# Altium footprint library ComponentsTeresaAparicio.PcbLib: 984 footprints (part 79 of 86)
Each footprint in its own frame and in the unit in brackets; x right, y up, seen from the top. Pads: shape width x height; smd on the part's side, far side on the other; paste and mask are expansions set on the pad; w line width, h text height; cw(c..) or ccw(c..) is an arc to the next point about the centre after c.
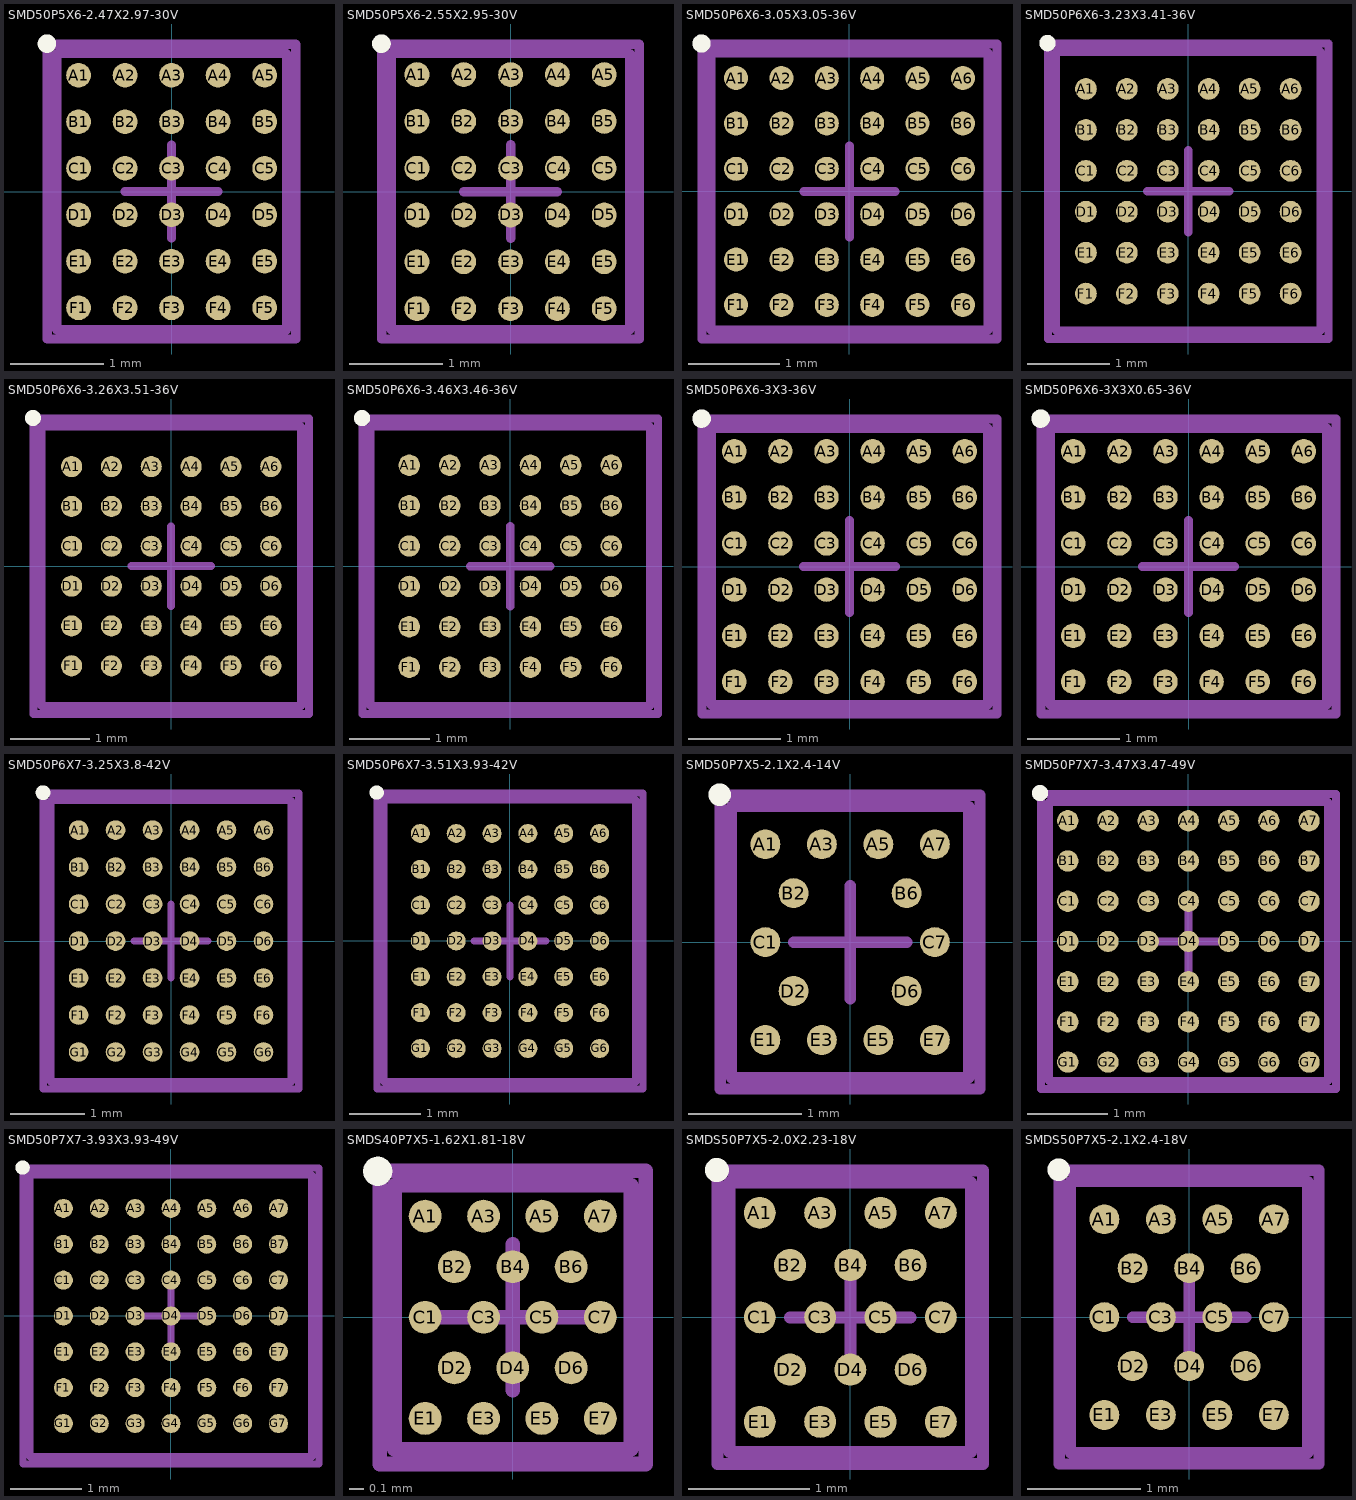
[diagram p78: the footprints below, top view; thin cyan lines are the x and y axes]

## SMD50P5X6-2.47X2.97-30V [mm] "Micro SMD, 30-Leads, Body 2.97x2.47mm, Pitch 0.5mm, NSC Recommended"
height 0.68
pads (30):
  round 0.265 smd paste-0.132 mask+0.05: A1(-1,1.25) A2(-0.5,1.25) A3(0,1.25) A4(0.5,1.25) A5(1,1.25) B1(-1,0.75) B2(-0.5,0.75) B3(0,0.75) B4(0.5,0.75) B5(1,0.75) C1(-1,0.25) C2(-0.5,0.25) C3(0,0.25) C4(0.5,0.25) C5(1,0.25) D1(-1,-0.25) D2(-0.5,-0.25) D3(0,-0.25) D4(0.5,-0.25) D5(1,-0.25) E1(-1,-0.75) E2(-0.5,-0.75) E3(0,-0.75) E4(0.5,-0.75) E5(1,-0.75) F1(-1,-1.25) F2(-0.5,-1.25) F3(0,-1.25) F4(0.5,-1.25) F5(1,-1.25)
Top Overlay:
  circle w0.1: c-1.34,1.59 r0.05
Top Paste:
  drawing of 270 lines, arcs and shapes, not listed
Mechanical 13:
  lines w0.1: -1.235,-1.485 -1.235,1.485 1.235,1.485 1.235,-1.485 -1.235,-1.485
Mechanical 15:
  lines w0.1: -0.5,0 0.5,0 ; 0,-0.5 0,0.5 ; -1.335,-1.585 -1.335,1.585 1.335,1.585 1.335,-1.585 -1.335,-1.585
3D body: height 0.68, standoff 0, extent -1.235,-1.49 1.235,1.49

## SMD50P5X6-2.55X2.95-30V [mm] "Micro SMD, 30-Leads, Body 2.95x2.55mm, Pitch 0.5mm, NSC Recommended"
height 0.68
pads (30):
  round 0.265 smd paste-0.132 mask+0.05: A1(-1,1.25) A2(-0.5,1.25) A3(0,1.25) A4(0.5,1.25) A5(1,1.25) B1(-1,0.75) B2(-0.5,0.75) B3(0,0.75) B4(0.5,0.75) B5(1,0.75) C1(-1,0.25) C2(-0.5,0.25) C3(0,0.25) C4(0.5,0.25) C5(1,0.25) D1(-1,-0.25) D2(-0.5,-0.25) D3(0,-0.25) D4(0.5,-0.25) D5(1,-0.25) E1(-1,-0.75) E2(-0.5,-0.75) E3(0,-0.75) E4(0.5,-0.75) E5(1,-0.75) F1(-1,-1.25) F2(-0.5,-1.25) F3(0,-1.25) F4(0.5,-1.25) F5(1,-1.25)
Top Overlay:
  circle w0.1: c-1.38,1.58 r0.05
Top Paste:
  drawing of 270 lines, arcs and shapes, not listed
Mechanical 13:
  lines w0.1: -1.275,-1.475 -1.275,1.475 1.275,1.475 1.275,-1.475 -1.275,-1.475
Mechanical 15:
  lines w0.1: -0.5,0 0.5,0 ; 0,-0.5 0,0.5 ; -1.375,-1.575 -1.375,1.575 1.375,1.575 1.375,-1.575 -1.375,-1.575
3D body: height 0.68, standoff 0, extent -1.274,-1.474 1.274,1.474

## SMD50P6X6-3.05X3.05-36V [mm] "Micro SMD, 36-Leads, Body 3.05x3.05mm, Pitch 0.5mm, NSC Recommended"
height 0.73
pads (36):
  round 0.265 smd paste-0.132 mask+0.05: A1(-1.25,1.25) A2(-0.75,1.25) A3(-0.25,1.25) A4(0.25,1.25) A5(0.75,1.25) A6(1.25,1.25) B1(-1.25,0.75) B2(-0.75,0.75) B3(-0.25,0.75) B4(0.25,0.75) B5(0.75,0.75) B6(1.25,0.75) C1(-1.25,0.25) C2(-0.75,0.25) C3(-0.25,0.25) C4(0.25,0.25) C5(0.75,0.25) C6(1.25,0.25) D1(-1.25,-0.25) D2(-0.75,-0.25) D3(-0.25,-0.25) D4(0.25,-0.25) D5(0.75,-0.25) D6(1.25,-0.25) E1(-1.25,-0.75) E2(-0.75,-0.75) E3(-0.25,-0.75) E4(0.25,-0.75) E5(0.75,-0.75) E6(1.25,-0.75) F1(-1.25,-1.25) F2(-0.75,-1.25) F3(-0.25,-1.25) F4(0.25,-1.25) F5(0.75,-1.25) F6(1.25,-1.25)
Top Overlay:
  circle w0.1: c-1.63,1.63 r0.05
Top Paste:
  drawing of 324 lines, arcs and shapes, not listed
Mechanical 13:
  lines w0.1: -1.525,-1.525 1.525,-1.525 1.525,1.525 -1.525,1.525 -1.525,-1.525
Mechanical 15:
  lines w0.1: -0.5,0 0.5,0 ; 0,-0.5 0,0.5 ; -1.625,-1.625 1.625,-1.625 1.625,1.625 -1.625,1.625 -1.625,-1.625
3D body: height 0.73, standoff 0, extent -1.524,-1.524 1.524,1.524

## SMD50P6X6-3.23X3.41-36V [mm] "Micro SMD, 36-Leads, Body 3.41x3.23mm, Pitch 0.5mm, NSC Recommended"
height 0.68
pads (36):
  round 0.265 smd paste-0.132 mask+0.05: A1(-1.25,1.25) A2(-0.75,1.25) A3(-0.25,1.25) A4(0.25,1.25) A5(0.75,1.25) A6(1.25,1.25) B1(-1.25,0.75) B2(-0.75,0.75) B3(-0.25,0.75) B4(0.25,0.75) B5(0.75,0.75) B6(1.25,0.75) C1(-1.25,0.25) C2(-0.75,0.25) C3(-0.25,0.25) C4(0.25,0.25) C5(0.75,0.25) C6(1.25,0.25) D1(-1.25,-0.25) D2(-0.75,-0.25) D3(-0.25,-0.25) D4(0.25,-0.25) D5(0.75,-0.25) D6(1.25,-0.25) E1(-1.25,-0.75) E2(-0.75,-0.75) E3(-0.25,-0.75) E4(0.25,-0.75) E5(0.75,-0.75) E6(1.25,-0.75) F1(-1.25,-1.25) F2(-0.75,-1.25) F3(-0.25,-1.25) F4(0.25,-1.25) F5(0.75,-1.25) F6(1.25,-1.25)
Top Overlay:
  circle w0.1: c-1.72,1.81 r0.05
Top Paste:
  drawing of 324 lines, arcs and shapes, not listed
Mechanical 13:
  lines w0.1: -1.615,-1.705 1.615,-1.705 1.615,1.705 -1.615,1.705 -1.615,-1.705
Mechanical 15:
  lines w0.1: -0.5,0 0.5,0 ; 0,-0.5 0,0.5 ; -1.715,-1.805 1.715,-1.805 1.715,1.805 -1.715,1.805 -1.715,-1.805
3D body: height 0.68, standoff 0, extent -1.614,-1.704 1.614,1.704

## SMD50P6X6-3.26X3.51-36V [mm] "Micro SMD, 36-Leads, Body 3.51x3.26mm, Pitch 0.5mm, NSC Recommended"
height 0.68
pads (36):
  round 0.265 smd paste-0.132 mask+0.05: A1(-1.25,1.25) A2(-0.75,1.25) A3(-0.25,1.25) A4(0.25,1.25) A5(0.75,1.25) A6(1.25,1.25) B1(-1.25,0.75) B2(-0.75,0.75) B3(-0.25,0.75) B4(0.25,0.75) B5(0.75,0.75) B6(1.25,0.75) C1(-1.25,0.25) C2(-0.75,0.25) C3(-0.25,0.25) C4(0.25,0.25) C5(0.75,0.25) C6(1.25,0.25) D1(-1.25,-0.25) D2(-0.75,-0.25) D3(-0.25,-0.25) D4(0.25,-0.25) D5(0.75,-0.25) D6(1.25,-0.25) E1(-1.25,-0.75) E2(-0.75,-0.75) E3(-0.25,-0.75) E4(0.25,-0.75) E5(0.75,-0.75) E6(1.25,-0.75) F1(-1.25,-1.25) F2(-0.75,-1.25) F3(-0.25,-1.25) F4(0.25,-1.25) F5(0.75,-1.25) F6(1.25,-1.25)
Top Overlay:
  circle w0.1: c-1.735,1.86 r0.05
Top Paste:
  drawing of 324 lines, arcs and shapes, not listed
Mechanical 13:
  lines w0.1: -1.63,-1.755 1.63,-1.755 1.63,1.755 -1.63,1.755 -1.63,-1.755
Mechanical 15:
  lines w0.1: -0.5,0 0.5,0 ; 0,-0.5 0,0.5 ; -1.73,-1.855 1.73,-1.855 1.73,1.855 -1.73,1.855 -1.73,-1.855
3D body: height 0.68, standoff 0, extent -1.629,-1.754 1.629,1.754

## SMD50P6X6-3.46X3.46-36V [mm] "Micro SMD, 36-Leads, Body 3.46x3.46mm, Pitch 0.5mm, NSC Recommended"
height 0.68
pads (36):
  round 0.265 smd paste-0.132 mask+0.05: A1(-1.25,1.25) A2(-0.75,1.25) A3(-0.25,1.25) A4(0.25,1.25) A5(0.75,1.25) A6(1.25,1.25) B1(-1.25,0.75) B2(-0.75,0.75) B3(-0.25,0.75) B4(0.25,0.75) B5(0.75,0.75) B6(1.25,0.75) C1(-1.25,0.25) C2(-0.75,0.25) C3(-0.25,0.25) C4(0.25,0.25) C5(0.75,0.25) C6(1.25,0.25) D1(-1.25,-0.25) D2(-0.75,-0.25) D3(-0.25,-0.25) D4(0.25,-0.25) D5(0.75,-0.25) D6(1.25,-0.25) E1(-1.25,-0.75) E2(-0.75,-0.75) E3(-0.25,-0.75) E4(0.25,-0.75) E5(0.75,-0.75) E6(1.25,-0.75) F1(-1.25,-1.25) F2(-0.75,-1.25) F3(-0.25,-1.25) F4(0.25,-1.25) F5(0.75,-1.25) F6(1.25,-1.25)
Top Overlay:
  circle w0.1: c-1.835,1.835 r0.05
Top Paste:
  drawing of 324 lines, arcs and shapes, not listed
Mechanical 13:
  lines w0.1: -1.73,-1.73 1.73,-1.73 1.73,1.73 -1.73,1.73 -1.73,-1.73
Mechanical 15:
  lines w0.1: -0.5,0 0.5,0 ; 0,-0.5 0,0.5 ; -1.83,-1.83 1.83,-1.83 1.83,1.83 -1.83,1.83 -1.83,-1.83
3D body: height 0.68, standoff 0, extent -1.73,-1.73 1.73,1.73

## SMD50P6X6-3X3-36V [mm] "Micro SMD, 36-Leads, Body 3x3mm, Pitch 0.5mm, NSC Recommended"
height 0.68
pads (36):
  round 0.265 smd paste-0.132 mask+0.05: A1(-1.25,1.25) A2(-0.75,1.25) A3(-0.25,1.25) A4(0.25,1.25) A5(0.75,1.25) A6(1.25,1.25) B1(-1.25,0.75) B2(-0.75,0.75) B3(-0.25,0.75) B4(0.25,0.75) B5(0.75,0.75) B6(1.25,0.75) C1(-1.25,0.25) C2(-0.75,0.25) C3(-0.25,0.25) C4(0.25,0.25) C5(0.75,0.25) C6(1.25,0.25) D1(-1.25,-0.25) D2(-0.75,-0.25) D3(-0.25,-0.25) D4(0.25,-0.25) D5(0.75,-0.25) D6(1.25,-0.25) E1(-1.25,-0.75) E2(-0.75,-0.75) E3(-0.25,-0.75) E4(0.25,-0.75) E5(0.75,-0.75) E6(1.25,-0.75) F1(-1.25,-1.25) F2(-0.75,-1.25) F3(-0.25,-1.25) F4(0.25,-1.25) F5(0.75,-1.25) F6(1.25,-1.25)
Top Overlay:
  circle w0.1: c-1.605,1.605 r0.05
Top Paste:
  drawing of 324 lines, arcs and shapes, not listed
Mechanical 13:
  lines w0.1: -1.5,-1.5 1.5,-1.5 1.5,1.5 -1.5,1.5 -1.5,-1.5
Mechanical 15:
  lines w0.1: -0.5,0 0.5,0 ; 0,-0.5 0,0.5 ; -1.6,-1.6 1.6,-1.6 1.6,1.6 -1.6,1.6 -1.6,-1.6
3D body: height 0.68, standoff 0, extent -1.499,-1.499 1.499,1.499

## SMD50P6X6-3X3X0.65-36V [mm] "Micro SMD, 36-Leads, Body 3x3mm, Pitch 0.5mm, NSC Recommended"
height 0.73
pads (36):
  round 0.265 smd paste-0.132 mask+0.05: A1(-1.25,1.25) A2(-0.75,1.25) A3(-0.25,1.25) A4(0.25,1.25) A5(0.75,1.25) A6(1.25,1.25) B1(-1.25,0.75) B2(-0.75,0.75) B3(-0.25,0.75) B4(0.25,0.75) B5(0.75,0.75) B6(1.25,0.75) C1(-1.25,0.25) C2(-0.75,0.25) C3(-0.25,0.25) C4(0.25,0.25) C5(0.75,0.25) C6(1.25,0.25) D1(-1.25,-0.25) D2(-0.75,-0.25) D3(-0.25,-0.25) D4(0.25,-0.25) D5(0.75,-0.25) D6(1.25,-0.25) E1(-1.25,-0.75) E2(-0.75,-0.75) E3(-0.25,-0.75) E4(0.25,-0.75) E5(0.75,-0.75) E6(1.25,-0.75) F1(-1.25,-1.25) F2(-0.75,-1.25) F3(-0.25,-1.25) F4(0.25,-1.25) F5(0.75,-1.25) F6(1.25,-1.25)
Top Overlay:
  circle w0.1: c-1.605,1.605 r0.05
Top Paste:
  drawing of 324 lines, arcs and shapes, not listed
Mechanical 13:
  lines w0.1: -1.5,-1.5 1.5,-1.5 1.5,1.5 -1.5,1.5 -1.5,-1.5
Mechanical 15:
  lines w0.1: -0.5,0 0.5,0 ; 0,-0.5 0,0.5 ; -1.6,-1.6 1.6,-1.6 1.6,1.6 -1.6,1.6 -1.6,-1.6
3D body: height 0.73, standoff 0, extent -1.499,-1.499 1.499,1.499

## SMD50P6X7-3.25X3.8-42V [mm] "Micro SMD, 42-Leads, Body 3.8x3.25mm, Pitch 0.5mm, NSC Recommended"
height 0.73
pads (42):
  round 0.265 smd paste-0.132 mask+0.05: A1(-1.25,1.5) A2(-0.75,1.5) A3(-0.25,1.5) A4(0.25,1.5) A5(0.75,1.5) A6(1.25,1.5) B1(-1.25,1) B2(-0.75,1) B3(-0.25,1) B4(0.25,1) B5(0.75,1) B6(1.25,1) C1(-1.25,0.5) C2(-0.75,0.5) C3(-0.25,0.5) C4(0.25,0.5) C5(0.75,0.5) C6(1.25,0.5) D1(-1.25,0) D2(-0.75,0) D3(-0.25,0) D4(0.25,0) D5(0.75,0) D6(1.25,0) E1(-1.25,-0.5) E2(-0.75,-0.5) E3(-0.25,-0.5) E4(0.25,-0.5) E5(0.75,-0.5) E6(1.25,-0.5) F1(-1.25,-1) F2(-0.75,-1) F3(-0.25,-1) F4(0.25,-1) F5(0.75,-1) F6(1.25,-1) G1(-1.25,-1.5) G2(-0.75,-1.5) G3(-0.25,-1.5) G4(0.25,-1.5) G5(0.75,-1.5) G6(1.25,-1.5)
Top Overlay:
  circle w0.1: c-1.73,2.005 r0.05
Top Paste:
  drawing of 378 lines, arcs and shapes, not listed
Mechanical 13:
  lines w0.1: -1.625,-1.9 -1.625,1.9 1.625,1.9 1.625,-1.9 -1.625,-1.9
Mechanical 15:
  lines w0.1: -0.5,0 0.5,0 ; 0,-0.5 0,0.5 ; -1.725,-2 -1.725,2 1.725,2 1.725,-2 -1.725,-2
3D body: height 0.73, standoff 0, extent -1.624,-1.899 1.624,1.899

## SMD50P6X7-3.51X3.93-42V [mm] "Micro SMD, 42-Leads, Body 3.93x3.51mm, Pitch 0.5mm, NSC Recommended"
height 0.68
pads (42):
  round 0.265 smd paste-0.132 mask+0.05: A1(-1.25,1.5) A2(-0.75,1.5) A3(-0.25,1.5) A4(0.25,1.5) A5(0.75,1.5) A6(1.25,1.5) B1(-1.25,1) B2(-0.75,1) B3(-0.25,1) B4(0.25,1) B5(0.75,1) B6(1.25,1) C1(-1.25,0.5) C2(-0.75,0.5) C3(-0.25,0.5) C4(0.25,0.5) C5(0.75,0.5) C6(1.25,0.5) D1(-1.25,0) D2(-0.75,0) D3(-0.25,0) D4(0.25,0) D5(0.75,0) D6(1.25,0) E1(-1.25,-0.5) E2(-0.75,-0.5) E3(-0.25,-0.5) E4(0.25,-0.5) E5(0.75,-0.5) E6(1.25,-0.5) F1(-1.25,-1) F2(-0.75,-1) F3(-0.25,-1) F4(0.25,-1) F5(0.75,-1) F6(1.25,-1) G1(-1.25,-1.5) G2(-0.75,-1.5) G3(-0.25,-1.5) G4(0.25,-1.5) G5(0.75,-1.5) G6(1.25,-1.5)
Top Overlay:
  circle w0.1: c-1.86,2.07 r0.05
Top Paste:
  drawing of 378 lines, arcs and shapes, not listed
Mechanical 13:
  lines w0.1: -1.755,-1.965 1.755,-1.965 1.755,1.965 -1.755,1.965 -1.755,-1.965
Mechanical 15:
  lines w0.1: -0.5,0 0.5,0 ; 0,-0.5 0,0.5 ; -1.855,-2.065 1.855,-2.065 1.855,2.065 -1.855,2.065 -1.855,-2.065
3D body: height 0.68, standoff 0, extent -1.754,-1.964 1.754,1.964

## SMD50P7X5-2.1X2.4-14V [mm] "Micro SMD, 18-Leads, Body 2.41x2.1mm, Pitch 0.5mm, NSC Recommended"
height 0.68
pads (14):
  round 0.265 smd paste-0.132 mask+0.05: A1(-0.75,0.866) A3(-0.25,0.866) A5(0.25,0.866) A7(0.75,0.866) B2(-0.5,0.433) B6(0.5,0.433) C1(-0.75,0) C7(0.75,0) D2(-0.5,-0.433) D6(0.5,-0.433) E1(-0.75,-0.866) E3(-0.25,-0.866) E5(0.25,-0.866) E7(0.75,-0.866)
Top Overlay:
  circle w0.1: c-1.155,1.305 r0.05
Top Paste:
  circle w0.05: c-0.7,0.816 r0.025
  circle w0.05: c-0.85,0.966 r0.025
  circle w0.05: c-0.85,0.816 r0.025
  circle w0.05: c-0.7,0.966 r0.025
  circle w0.05: c0.85,0.816 r0.025
  circle w0.05: c0.7,0.966 r0.025
  circle w0.05: c0.7,0.816 r0.025
  circle w0.05: c0.85,0.966 r0.025
  circle w0.05: c0.85,-0.816 r0.025
  circle w0.05: c0.7,-0.966 r0.025
  circle w0.05: c0.7,-0.816 r0.025
  circle w0.05: c0.85,-0.966 r0.025
  circle w0.05: c-0.7,-0.966 r0.025
  circle w0.05: c-0.85,-0.816 r0.025
  circle w0.05: c-0.85,-0.966 r0.025
  circle w0.05: c-0.7,-0.816 r0.025
  circle w0.05: c0.575,0.508 r0.025
  circle w0.05: c0.425,0.358 r0.025
  circle w0.05: c0.425,0.508 r0.025
  circle w0.05: c0.575,0.358 r0.025
  circle w0.05: c0.325,0.816 r0.025
  circle w0.05: c0.175,0.966 r0.025
  circle w0.05: c0.175,0.816 r0.025
  circle w0.05: c0.325,0.966 r0.025
  circle w0.05: c-0.175,0.816 r0.025
  circle w0.05: c-0.325,0.966 r0.025
  circle w0.05: c-0.325,0.816 r0.025
  circle w0.05: c-0.175,0.966 r0.025
  circle w0.05: c0.575,-0.508 r0.025
  circle w0.05: c0.425,-0.358 r0.025
  circle w0.05: c0.425,-0.508 r0.025
  circle w0.05: c0.575,-0.358 r0.025
  circle w0.05: c-0.425,0.358 r0.025
  circle w0.05: c-0.575,0.508 r0.025
  circle w0.05: c-0.575,0.358 r0.025
  circle w0.05: c-0.425,0.508 r0.025
  circle w0.05: c-0.7,-0.075 r0.025
  circle w0.05: c-0.85,0.075 r0.025
  circle w0.05: c-0.85,-0.075 r0.025
  circle w0.05: c-0.7,0.075 r0.025
  circle w0.05: c-0.425,-0.358 r0.025
  circle w0.05: c-0.575,-0.508 r0.025
  circle w0.05: c-0.575,-0.358 r0.025
  circle w0.05: c-0.425,-0.508 r0.025
  circle w0.05: c0.325,-0.816 r0.025
  circle w0.05: c0.175,-0.966 r0.025
  circle w0.05: c0.175,-0.816 r0.025
  circle w0.05: c0.325,-0.966 r0.025
  circle w0.05: c-0.175,-0.816 r0.025
  circle w0.05: c-0.325,-0.966 r0.025
  circle w0.05: c-0.325,-0.816 r0.025
  circle w0.05: c-0.175,-0.966 r0.025
  circle w0.05: c0.85,0.075 r0.025
  circle w0.05: c0.7,-0.075 r0.025
  circle w0.05: c0.7,0.075 r0.025
  circle w0.05: c0.85,-0.075 r0.025
  region: -0.85,0.966 -0.85,0.816 -0.7,0.816 -0.7,0.966
  region: -0.65,0.816 -0.65,0.966 -0.7,0.966 -0.7,0.816
  region: -0.7,1.016 -0.85,1.016 -0.85,0.966 -0.7,0.966
  region: -0.9,0.966 -0.9,0.816 -0.85,0.816 -0.85,0.966
  rectangle: -0.85,0.766 -0.7,0.816
  region: 0.7,0.966 0.7,0.816 0.85,0.816 0.85,0.966
  region: 0.9,0.816 0.9,0.966 0.85,0.966 0.85,0.816
  region: 0.85,1.016 0.7,1.016 0.7,0.966 0.85,0.966
  region: 0.65,0.966 0.65,0.816 0.7,0.816 0.7,0.966
  rectangle: 0.7,0.766 0.85,0.816
  rectangle: 0.7,-1.016 0.85,-0.966
  region: 0.65,-0.816 0.65,-0.966 0.7,-0.966 0.7,-0.816
  region: 0.85,-0.766 0.7,-0.766 0.7,-0.816 0.85,-0.816
  region: 0.9,-0.966 0.9,-0.816 0.85,-0.816 0.85,-0.966
  region: 0.7,-0.816 0.7,-0.966 0.85,-0.966 0.85,-0.816
  region: -0.85,-0.816 -0.85,-0.966 -0.7,-0.966 -0.7,-0.816
  region: -0.65,-0.966 -0.65,-0.816 -0.7,-0.816 -0.7,-0.966
  region: -0.7,-0.766 -0.85,-0.766 -0.85,-0.816 -0.7,-0.816
  region: -0.9,-0.816 -0.9,-0.966 -0.85,-0.966 -0.85,-0.816
  rectangle: -0.85,-1.016 -0.7,-0.966
  rectangle: 0.425,0.308 0.575,0.358
  region: 0.375,0.508 0.375,0.358 0.425,0.358 0.425,0.508
  region: 0.575,0.558 0.425,0.558 0.425,0.508 0.575,0.508
  region: 0.625,0.358 0.625,0.508 0.575,0.508 0.575,0.358
  region: 0.425,0.508 0.425,0.358 0.575,0.358 0.575,0.508
  region: 0.175,0.966 0.175,0.816 0.325,0.816 0.325,0.966
  region: 0.375,0.816 0.375,0.966 0.325,0.966 0.325,0.816
  region: 0.325,1.016 0.175,1.016 0.175,0.966 0.325,0.966
  region: 0.125,0.966 0.125,0.816 0.175,0.816 0.175,0.966
  rectangle: 0.175,0.766 0.325,0.816
  region: -0.325,0.966 -0.325,0.816 -0.175,0.816 -0.175,0.966
  region: -0.125,0.816 -0.125,0.966 -0.175,0.966 -0.175,0.816
  region: -0.175,1.016 -0.325,1.016 -0.325,0.966 -0.175,0.966
  region: -0.375,0.966 -0.375,0.816 -0.325,0.816 -0.325,0.966
  rectangle: -0.325,0.766 -0.175,0.816
  region: 0.425,-0.358 0.425,-0.508 0.575,-0.508 0.575,-0.358
  region: 0.625,-0.508 0.625,-0.358 0.575,-0.358 0.575,-0.508
  region: 0.575,-0.308 0.425,-0.308 0.425,-0.358 0.575,-0.358
  region: 0.375,-0.358 0.375,-0.508 0.425,-0.508 0.425,-0.358
  rectangle: 0.425,-0.558 0.575,-0.508
  region: -0.575,0.508 -0.575,0.358 -0.425,0.358 -0.425,0.508
  region: -0.375,0.358 -0.375,0.508 -0.425,0.508 -0.425,0.358
  region: -0.425,0.558 -0.575,0.558 -0.575,0.508 -0.425,0.508
  region: -0.625,0.508 -0.625,0.358 -0.575,0.358 -0.575,0.508
  rectangle: -0.575,0.308 -0.425,0.358
  region: -0.85,0.075 -0.85,-0.075 -0.7,-0.075 -0.7,0.075
  region: -0.65,-0.075 -0.65,0.075 -0.7,0.075 -0.7,-0.075
  region: -0.7,0.125 -0.85,0.125 -0.85,0.075 -0.7,0.075
  region: -0.9,0.075 -0.9,-0.075 -0.85,-0.075 -0.85,0.075
  rectangle: -0.85,-0.125 -0.7,-0.075
  rectangle: -0.575,-0.558 -0.425,-0.508
  region: -0.625,-0.358 -0.625,-0.508 -0.575,-0.508 -0.575,-0.358
  region: -0.425,-0.308 -0.575,-0.308 -0.575,-0.358 -0.425,-0.358
  region: -0.375,-0.508 -0.375,-0.358 -0.425,-0.358 -0.425,-0.508
  region: -0.575,-0.358 -0.575,-0.508 -0.425,-0.508 -0.425,-0.358
  rectangle: 0.175,-1.016 0.325,-0.966
  region: 0.125,-0.816 0.125,-0.966 0.175,-0.966 0.175,-0.816
  region: 0.325,-0.766 0.175,-0.766 0.175,-0.816 0.325,-0.816
  region: 0.375,-0.966 0.375,-0.816 0.325,-0.816 0.325,-0.966
  region: 0.175,-0.816 0.175,-0.966 0.325,-0.966 0.325,-0.816
  rectangle: -0.325,-1.016 -0.175,-0.966
  region: -0.375,-0.816 -0.375,-0.966 -0.325,-0.966 -0.325,-0.816
  region: -0.175,-0.766 -0.325,-0.766 -0.325,-0.816 -0.175,-0.816
  region: -0.125,-0.966 -0.125,-0.816 -0.175,-0.816 -0.175,-0.966
  region: -0.325,-0.816 -0.325,-0.966 -0.175,-0.966 -0.175,-0.816
  rectangle: 0.7,-0.125 0.85,-0.075
  region: 0.65,0.075 0.65,-0.075 0.7,-0.075 0.7,0.075
  region: 0.85,0.125 0.7,0.125 0.7,0.075 0.85,0.075
  region: 0.9,-0.075 0.9,0.075 0.85,0.075 0.85,-0.075
  region: 0.7,0.075 0.7,-0.075 0.85,-0.075 0.85,0.075
Mechanical 13:
  lines w0.1: -1.05,-1.2 -1.05,1.2 1.05,1.2 1.05,-1.2 -1.05,-1.2
Mechanical 15:
  lines w0.1: -0.5,0 0.5,0 ; 0,-0.5 0,0.5 ; -1.15,-1.3 1.15,-1.3 1.15,1.3 -1.15,1.3 -1.15,-1.3
3D body: height 0.68, standoff 0, extent -1.049,-1.199 1.049,1.199

## SMD50P7X7-3.47X3.47-49V [mm] "Micro SMD, 49-Leads, Body 3.47x3.47mm, Pitch 0.5mm, NSC Recommended"
height 0.73
pads (49):
  round 0.265 smd paste-0.132 mask+0.05: A1(-1.5,1.5) A2(-1,1.5) A3(-0.5,1.5) A4(0,1.5) A5(0.5,1.5) A6(1,1.5) A7(1.5,1.5) B1(-1.5,1) B2(-1,1) B3(-0.5,1) B4(0,1) B5(0.5,1) B6(1,1) B7(1.5,1) C1(-1.5,0.5) C2(-1,0.5) C3(-0.5,0.5) C4(0,0.5) C5(0.5,0.5) C6(1,0.5) C7(1.5,0.5) D1(-1.5,0) D2(-1,0) D3(-0.5,0) D4(0,0) D5(0.5,0) D6(1,0) D7(1.5,0) E1(-1.5,-0.5) E2(-1,-0.5) E3(-0.5,-0.5) E4(0,-0.5) E5(0.5,-0.5) E6(1,-0.5) E7(1.5,-0.5) F1(-1.5,-1) F2(-1,-1) F3(-0.5,-1) F4(0,-1) F5(0.5,-1) F6(1,-1) F7(1.5,-1) G1(-1.5,-1.5) G2(-1,-1.5) G3(-0.5,-1.5) G4(0,-1.5) G5(0.5,-1.5) G6(1,-1.5) G7(1.5,-1.5)
Top Overlay:
  circle w0.1: c-1.845,1.845 r0.05
Top Paste:
  drawing of 441 lines, arcs and shapes, not listed
Mechanical 13:
  lines w0.1: -1.735,-1.735 1.735,-1.735 1.735,1.735 -1.735,1.735 -1.735,-1.735
Mechanical 15:
  lines w0.1: -0.5,0 0.5,0 ; 0,-0.5 0,0.5 ; -1.835,-1.835 1.835,-1.835 1.835,1.835 -1.835,1.835 -1.835,-1.835
3D body: height 0.73, standoff 0, extent -1.734,-1.734 1.734,1.734

## SMD50P7X7-3.93X3.93-49V [mm] "Micro SMD, 49-Leads, Body 3.93x3.93mm, Pitch 0.5mm, NSC Recommended"
height 0.73
pads (49):
  round 0.265 smd paste-0.132 mask+0.05: A1(-1.5,1.5) A2(-1,1.5) A3(-0.5,1.5) A4(0,1.5) A5(0.5,1.5) A6(1,1.5) A7(1.5,1.5) B1(-1.5,1) B2(-1,1) B3(-0.5,1) B4(0,1) B5(0.5,1) B6(1,1) B7(1.5,1) C1(-1.5,0.5) C2(-1,0.5) C3(-0.5,0.5) C4(0,0.5) C5(0.5,0.5) C6(1,0.5) C7(1.5,0.5) D1(-1.5,0) D2(-1,0) D3(-0.5,0) D4(0,0) D5(0.5,0) D6(1,0) D7(1.5,0) E1(-1.5,-0.5) E2(-1,-0.5) E3(-0.5,-0.5) E4(0,-0.5) E5(0.5,-0.5) E6(1,-0.5) E7(1.5,-0.5) F1(-1.5,-1) F2(-1,-1) F3(-0.5,-1) F4(0,-1) F5(0.5,-1) F6(1,-1) F7(1.5,-1) G1(-1.5,-1.5) G2(-1,-1.5) G3(-0.5,-1.5) G4(0,-1.5) G5(0.5,-1.5) G6(1,-1.5) G7(1.5,-1.5)
Top Overlay:
  circle w0.1: c-2.07,2.07 r0.05
Top Paste:
  drawing of 441 lines, arcs and shapes, not listed
Mechanical 13:
  lines w0.1: -1.965,-1.965 1.965,-1.965 1.965,1.965 -1.965,1.965 -1.965,-1.965
Mechanical 15:
  lines w0.1: -0.5,0 0.5,0 ; 0,-0.5 0,0.5 ; -2.065,-2.065 2.065,-2.065 2.065,2.065 -2.065,2.065 -2.065,-2.065
3D body: height 0.73, standoff 0, extent -1.964,-1.964 1.964,1.964

## SMDS40P7X5-1.62X1.81-18V [mm] "Micro SMD, 18-Leads, Body 1.81x1.62mm, Pitch 0.4mm, NSC Recommended"
height 0.68
pads (18):
  round 0.225 smd paste-0.112 mask+0.05: A1(-0.6,0.693) A3(-0.2,0.693) A5(0.2,0.693) A7(0.6,0.693) B2(-0.4,0.346) B4(0,0.346) B6(0.4,0.346) C1(-0.6,0) C3(-0.2,0) C5(0.2,0) C7(0.6,0) D2(-0.4,-0.346) D4(0,-0.346) D6(0.4,-0.346) E1(-0.6,-0.693) E3(-0.2,-0.693) E5(0.2,-0.693) E7(0.6,-0.693)
Top Overlay:
  circle w0.1: c-0.925,1 r0.05
Top Paste:
  drawing of 162 lines, arcs and shapes, not listed
Mechanical 13:
  lines w0.1: -0.81,-0.905 -0.81,0.905 0.81,0.905 0.81,-0.905 -0.81,-0.905
Mechanical 15:
  lines w0.1: -0.5,0 0.5,0 ; 0,-0.5 0,0.5 ; -0.91,-1.005 0.91,-1.005 0.91,1.005 -0.91,1.005 -0.91,-1.005
3D body: height 0.68, standoff 0, extent -0.809,-0.904 0.809,0.904

## SMDS50P7X5-2.0X2.23-18V [mm] "Micro SMD, 18-Leads, Body 2.23x2.0mm, Pitch 0.5mm, NSC Recommended"
height 0.68
pads (18):
  round 0.265 smd paste-0.132 mask+0.05: A1(-0.75,0.866) A3(-0.25,0.866) A5(0.25,0.866) A7(0.75,0.866) B2(-0.5,0.433) B4(0,0.433) B6(0.5,0.433) C1(-0.75,0) C3(-0.25,0) C5(0.25,0) C7(0.75,0) D2(-0.5,-0.433) D4(0,-0.433) D6(0.5,-0.433) E1(-0.75,-0.866) E3(-0.25,-0.866) E5(0.25,-0.866) E7(0.75,-0.866)
Top Overlay:
  circle w0.1: c-1.105,1.22 r0.05
Top Paste:
  drawing of 162 lines, arcs and shapes, not listed
Mechanical 13:
  lines w0.1: -1,-1.115 -1,1.115 1,1.115 1,-1.115 -1,-1.115
Mechanical 15:
  lines w0.1: -0.5,0 0.5,0 ; 0,-0.5 0,0.5 ; -1.1,-1.215 -1.1,1.215 1.1,1.215 1.1,-1.215 -1.1,-1.215
3D body: height 0.68, standoff 0, extent -0.999,-1.114 0.999,1.114

## SMDS50P7X5-2.1X2.4-18V [mm] "Micro SMD, 18-Leads, Body 2.41x2.1mm, Pitch 0.5mm, NSC Recommended"
height 0.68
pads (18):
  round 0.265 smd paste-0.132 mask+0.05: A1(-0.75,0.866) A3(-0.25,0.866) A5(0.25,0.866) A7(0.75,0.866) B2(-0.5,0.433) B4(0,0.433) B6(0.5,0.433) C1(-0.75,0) C3(-0.25,0) C5(0.25,0) C7(0.75,0) D2(-0.5,-0.433) D4(0,-0.433) D6(0.5,-0.433) E1(-0.75,-0.866) E3(-0.25,-0.866) E5(0.25,-0.866) E7(0.75,-0.866)
Top Overlay:
  circle w0.1: c-1.155,1.305 r0.05
Top Paste:
  drawing of 162 lines, arcs and shapes, not listed
Mechanical 13:
  lines w0.1: -1.05,-1.2 1.05,-1.2 1.05,1.2 -1.05,1.2 -1.05,-1.2
Mechanical 15:
  lines w0.1: -0.5,0 0.5,0 ; 0,-0.5 0,0.5 ; -1.15,-1.3 -1.15,1.3 1.15,1.3 1.15,-1.3 -1.15,-1.3
3D body: height 0.68, standoff 0, extent -1.049,-1.2 1.049,1.199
